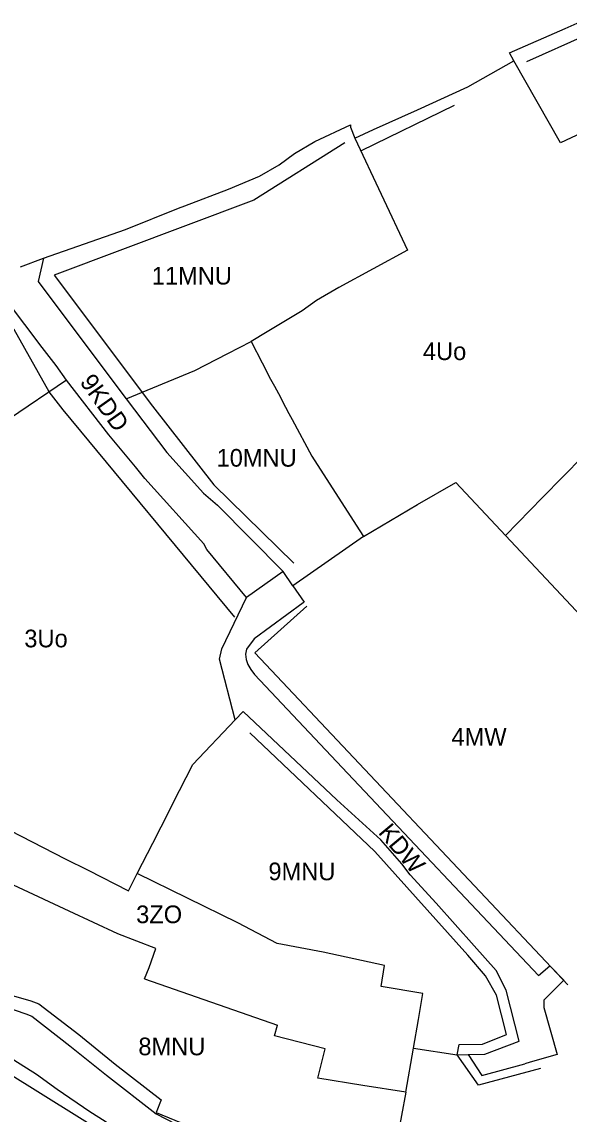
# Model space of a CAD drawing. Extents: x 7422310 to 7423642, y 5546060 to 5546927.
# Drawn here: x 7422901 to 7423055.8, y 5546433.5 to 5546742.6 of the extents above; entities that cross this region are included whole.
import ezdxf

# ---------------------------------------------------------------- set-up
doc = ezdxf.new("R2010")
doc.units = 0
for name, color, linetype in [('linie_rozgraniczajace', 7, 'Continuous'), ('linie_zabudowy_nieprzekraczalne', 7, 'Continuous'), ('oznaczenia_przeznaczen', 7, 'Continuous')]:
    doc.layers.add(name, color=color, linetype=linetype)

msp = doc.modelspace()

# ---------------------------------------------------------------- linework, layer by layer
at = {"layer": 'linie_rozgraniczajace'}
for p, q in [((7422974.92, 5546587.08), (7422964.54, 5546579.76)), ((7422937, 5546475.03), (7422938.84, 5546480.42)), ((7423003.58, 5546475.62), (7422986.25, 5546479.34)), ((7422935.72, 5546471.84), (7422937, 5546475.03)), ((7423002.64, 5546469.68), (7423003.58, 5546475.62)), ((7422935.72, 5546471.84), (7422973.27, 5546458.71)), ((7422972.46, 5546455.72), (7422973.27, 5546458.71)), ((7423009.63, 5546439.75), (7423004.81, 5546414.23))]:
    msp.add_line(p, q, dxfattribs=at)
for points in [[(7422900.64, 5546673.26), (7422907.12, 5546675.71), (7422930.31, 5546683.88), (7422945.25, 5546689.84), (7422947.1, 5546690.58), (7422959.43, 5546695.29), (7422968.2, 5546698.93), (7422973.81, 5546702.14), (7422978.12, 5546705.31), (7422983.86, 5546708.75), (7422993.98, 5546713.49), (7422993.98, 5546712.83), (7422995.21, 5546709.7), (7423000.48, 5546712.12), (7423012.92, 5546717.72), (7423027.15, 5546724.2), (7423040.12, 5546731.59), (7423038.89, 5546733.83), (7423054.69, 5546740.72), (7423058.92, 5546742.6)], [(7423068.24, 5546715.33), (7423053.34, 5546708.35), (7423040.12, 5546731.59)], [(7422995.21, 5546709.7), (7423010.06, 5546678.04), (7422990.63, 5546667.48), (7422984.37, 5546663.79), (7422980.25, 5546660.84), (7422970.39, 5546654.89), (7422965.89, 5546652.19), (7422969, 5546646.14), (7422971.28, 5546641.49), (7422972.47, 5546639.55), (7422973.58, 5546637.42), (7422975.55, 5546633.57), (7422976.53, 5546631.74), (7422977.44, 5546630.05), (7422982.98, 5546619.69), (7422995.56, 5546600.16), (7422997.59, 5546596.97), (7423012.89, 5546606.05), (7423023.73, 5546612.22), (7423037.77, 5546597.26), (7423048.23, 5546608.02), (7423059.72, 5546619.68)], [(7422907.12, 5546675.71), (7422905.64, 5546669.1), (7422918.56, 5546651.83), (7422930.45, 5546635.92), (7422942.03, 5546620.76), (7422952.34, 5546609.26), (7422956.3, 5546605.86), (7422974.92, 5546587.08)], [(7422913.66, 5546641.25), (7422910.73, 5546645.35), (7422906.74, 5546650.45), (7422891.91, 5546669.94)], [(7422930.45, 5546635.92), (7422949.91, 5546643.96), (7422959.22, 5546648.74), (7422965.89, 5546652.19)], [(7422956.87, 5546562.28), (7422957.53, 5546565.21), (7422964.54, 5546579.76), (7422953.34, 5546593.34), (7422952.43, 5546594.95), (7422935.81, 5546613.41), (7422933.16, 5546616.65), (7422925.56, 5546625.75), (7422913.66, 5546641.25), (7422897.54, 5546630.3)], [(7422997.59, 5546596.97), (7422977.64, 5546583.06), (7422974.92, 5546587.08)], [(7423088.62, 5546547.39), (7423085.49, 5546547.74), (7423075.14, 5546558.24), (7423067.43, 5546566.16), (7423057.78, 5546575.97), (7423037.77, 5546597.26)], [(7422977.64, 5546583.06), (7422980.82, 5546578.37), (7422980.54, 5546578.17), (7422966.65, 5546568.06), (7422964.51, 5546565.12), (7422964.2, 5546563.64), (7422964.4, 5546562.19), (7422964.94, 5546560.79), (7422965.73, 5546559.37), (7422966.83, 5546557.97), (7422991.57, 5546531.65), (7423047.09, 5546472.78), (7423050.31, 5546475.53), (7423054.3, 5546471.42), (7423048.64, 5546465.77), (7423048.6, 5546463.71), (7423052.36, 5546450.37), (7423044.73, 5546448.22), (7423043.29, 5546447.81)], [(7422894.46, 5546515.44), (7422913.24, 5546505.76), (7422919.75, 5546502.53), (7422931.12, 5546496.76), (7422933.58, 5546501.58), (7422938.01, 5546510.24), (7422942.72, 5546519.45), (7422943.71, 5546521.39), (7422949.31, 5546532.44), (7422961.29, 5546545.1), (7422956.87, 5546562.28)], [(7423041.64, 5546454.21), (7423037.94, 5546468.57), (7423035.17, 5546474.21), (7423028.95, 5546481.17), (7423018.19, 5546493.21), (7423010.77, 5546501.28), (7423008.46, 5546504.32), (7423002.54, 5546511.12), (7422990.05, 5546522.44), (7422963.59, 5546547.43), (7422961.29, 5546545.1)], [(7422938.84, 5546480.42), (7422928.13, 5546484.56), (7422914.39, 5546490.97), (7422874.08, 5546509.77)], [(7422986.25, 5546479.34), (7422973.23, 5546481.86), (7422962.12, 5546487.63), (7422933.58, 5546501.58)], [(7423013.2, 5546460.34), (7423014.4, 5546467.7), (7423002.64, 5546469.68)], [(7422942.84, 5546418.27), (7422938.07, 5546422.01), (7422924.52, 5546431.41), (7422920.21, 5546434.18), (7422910.98, 5546440.54), (7422905.16, 5546444.71), (7422898.7, 5546448.79), (7422895.11, 5546450.46), (7422890.01, 5546452.75), (7422875.8, 5546457.17), (7422869.23, 5546459.14), (7422867.87, 5546459.46), (7422850.77, 5546464.93), (7422848.28, 5546453.48), (7422850.16, 5546448.92), (7422858.34, 5546432.53), (7422866.53, 5546416.28), (7422868.25, 5546412.95), (7422873.93, 5546400.01), (7422878.61, 5546392.2), (7422880.68, 5546389.97), (7422882.72, 5546383.91)], [(7422896.1, 5546464.02), (7422902.1, 5546461.88), (7422903.84, 5546461.21), (7422914.58, 5546452.89), (7422924.93, 5546444.52), (7422939, 5546433.61), (7422964.13, 5546420.6), (7422979.3, 5546417.43), (7422992.67, 5546414.98), (7423004.81, 5546414.23), (7423018.96, 5546414.36), (7423042.15, 5546415.05)], [(7423009.63, 5546439.75), (7423011.79, 5546452.2), (7423013.2, 5546460.34)], [(7423009.63, 5546439.75), (7422997.39, 5546441.67), (7422984.69, 5546443.67), (7422986.8, 5546452.03), (7422972.46, 5546455.72)], [(7423024.14, 5546450.27), (7423027.2, 5546450.37), (7423031.89, 5546450.53), (7423041.64, 5546454.21)], [(7423011.79, 5546452.2), (7423024.14, 5546450.27)], [(7423027.2, 5546450.37), (7423031.06, 5546444.51), (7423043.29, 5546447.81)]]:
    msp.add_lwpolyline(points, dxfattribs=at)
at = {"layer": 'linie_zabudowy_nieprzekraczalne'}
for p, q in [((7423023.3, 5546718.97), (7422996.96, 5546706.13)), ((7422992.32, 5546708.41), (7422966.56, 5546692.11)), ((7422966.56, 5546692.11), (7422910.13, 5546670.92)), ((7422910.13, 5546670.92), (7422937.94, 5546633.86)), ((7423031.3, 5546453.3), (7423038.1, 5546456.08)), ((7423024.68, 5546453.28), (7423031.3, 5546453.3)), ((7423047.7, 5546446.47), (7423030.19, 5546441.73))]:
    msp.add_line(p, q, dxfattribs=at)
for points in [[(7423066.11, 5546740.49), (7423060.55, 5546738.86), (7423043.75, 5546731.25)], [(7422912.68, 5546632.8), (7422908.69, 5546637.87), (7422898.8, 5546655.56), (7422892.13, 5546664.22)], [(7422961.22, 5546574.19), (7422912.68, 5546632.8)], [(7422937.94, 5546633.86), (7422955.29, 5546611.59), (7422977.94, 5546589.44)], [(7422817.6, 5546579.63), (7422819.93, 5546569.76), (7422826.39, 5546538.55), (7422828.76, 5546528.49), (7422832.66, 5546510.34), (7422835.47, 5546499.79), (7422835.47, 5546499.79), (7422844.72, 5546490.18), (7422857.98, 5546482.57), (7422868.51, 5546476.06), (7422868.51, 5546476.06), (7422880.09, 5546472.18), (7422890.18, 5546469.32), (7422897.29, 5546467.43), (7422903.49, 5546465.63), (7422905.82, 5546464.74), (7422917.06, 5546456.03), (7422927.41, 5546447.65), (7422940.37, 5546437.61)], [(7422981.6, 5546577.23), (7422966.9, 5546564.02), (7423055.42, 5546470.15), (7423055.42, 5546470.15)], [(7423027.08, 5546478.56), (7423000.84, 5546507.84), (7422965.48, 5546541.44), (7422965.48, 5546541.44), (7422965.48, 5546541.44)], [(7423038.1, 5546456.08), (7423035.26, 5546467.17), (7423032.15, 5546472.65), (7423027.08, 5546478.56)], [(7423030.19, 5546441.73), (7423024.14, 5546450.27), (7423024.68, 5546453.28)], [(7422942.78, 5546414.42), (7422941.94, 5546415.53), (7422937.13, 5546420.13), (7422896.78, 5546445.27)], [(7422940.37, 5546437.61), (7422939.01, 5546434.04)], [(7422939.01, 5546434.04), (7422951.6, 5546428.79), (7422952.33, 5546430.62)]]:
    msp.add_lwpolyline(points, dxfattribs=at)

# ---------------------------------------------------------------- texts
at = {"layer": 'oznaczenia_przeznaczen'}
for s, p in [('11MNU', (7422937.73, 5546668.27)), ('4Uo', (7423014.42, 5546646.9)), ('10MNU', (7422956.06, 5546616.74)), ('3Uo', (7422901.69, 5546565.62)), ('4MW', (7423022.5, 5546537.8)), ('9MNU', (7422970.73, 5546499.71)), ('3ZO', (7422933.32, 5546487.57)), ('8MNU', (7422933.95, 5546450.19))]:
    msp.add_text(s, height=5, dxfattribs=at).set_placement(p)
for s, rotation, p in [('9KDD', 305.3415, (7422917.21, 5546640.68)), ('KDW', 309.9032, (7423001.58, 5546513.13))]:
    msp.add_text(s, height=5, rotation=rotation, dxfattribs=at).set_placement(p)

doc.saveas('drawing.dxf')
